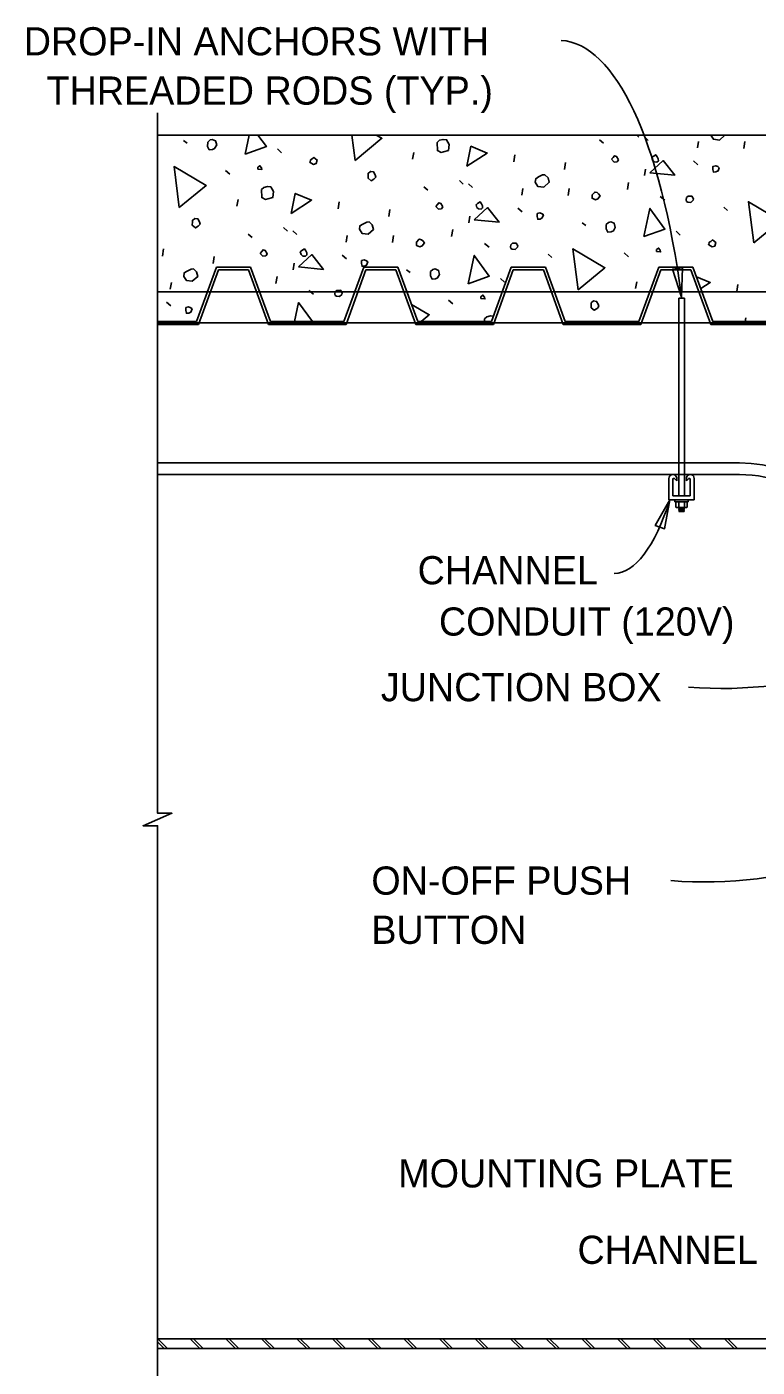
# Model space of a CAD drawing. Extents: x 927736.2 to 927809.6, y 636703.6 to 636757.7.
# Drawn here: x 927784.6 to 927794.26, y 636715.22 to 636732.95 of the extents above; entities that cross this region are included whole.
import ezdxf

# ---------------------------------------------------------------- set-up
doc = ezdxf.new("R2010")
doc.units = 0
for name, color, linetype in [('DimLines_dp', 7, 'Continuous'), ('Miscellaneous1', 7, 'Continuous'), ('Miscellaneous2', 7, 'Continuous'), ('Miscellaneous3', 7, 'Continuous')]:
    doc.layers.add(name, color=color, linetype=linetype)

msp = doc.modelspace()

# ---------------------------------------------------------------- linework, layer by layer
at = {"layer": 'DimLines_dp'}
msp.add_lwpolyline([(927786.333, 636713.104), (927786.333, 636722.378), (927786.142, 636722.378), (927786.333, 636722.461), (927786.524, 636722.544), (927786.333, 636722.544), (927786.333, 636731.807)], dxfattribs=at)
for points in [[(927793.262, 636729.37), (927793.144, 636729.742), (927793.273, 636729.76)], [(927793.108, 636726.69), (927792.915, 636726.351), (927793.038, 636726.306)]]:
    msp.add_lwpolyline(points, close=True, dxfattribs=at)
for centre in [(927793.802, 636729.733), (927793.57, 636727.173)]:
    msp.add_arc(centre, 5.539, 265.3641, 288.9731, dxfattribs=at)
for centre, major_axis, ratio, start_param, end_param in [((927791.283, 636725.568), (-0.388, -7.199), 0.2923, 2.142822, 3.141563), ((927792.341, 636729.829), (-0.032, 4.113), 0.280094, 3.141615, 3.84244)]:
    msp.add_ellipse(centre, major_axis=major_axis, ratio=ratio, start_param=start_param, end_param=end_param, dxfattribs=at)
at = {"layer": 'Miscellaneous1'}
for p, q in [((927794.029, 636727.179), (927786.333, 636727.179)), ((927794.029, 636727.024), (927786.333, 636727.024)), ((927793.095, 636726.973), (927793.095, 636726.69)), ((927793.146, 636726.742), (927793.146, 636726.961)), ((927793.168, 636726.97), (927793.198, 636726.941)), ((927793.198, 636726.985), (927793.192, 636726.996)), ((927793.198, 636726.941), (927793.198, 636726.985)), ((927793.332, 636726.996), (927793.326, 636726.985)), ((927793.326, 636726.985), (927793.326, 636726.941)), ((927793.326, 636726.941), (927793.356, 636726.97)), ((927793.378, 636726.961), (927793.378, 636726.742)), ((927793.429, 636726.69), (927793.429, 636726.973)), ((927793.095, 636726.69), (927793.429, 636726.69)), ((927793.378, 636726.742), (927793.146, 636726.742))]:
    msp.add_line(p, q, dxfattribs=at)
for centre, radius, start, end in [((927794.029, 636725.374), 1.804, 14.3572, 89.9857), ((927793.146, 636726.973), 0.0513, 26.1794, 179.9999), ((927793.159, 636726.961), 0.0128, 45, 180), ((927793.378, 636726.973), 0.0513, 0.0001, 153.8206), ((927793.365, 636726.961), 0.0128, 360, 135), ((927794.029, 636725.374), 1.65, 0, 90)]:
    msp.add_arc(centre, radius, start, end, dxfattribs=at)
at = {"layer": 'Miscellaneous2'}
for p, q in [((927786.333, 636731.515), (927803.622, 636731.515)), ((927786.677, 636731.445), (927786.725, 636731.407)), ((927792.178, 636731.451), (927792.228, 636731.407)), ((927792.67, 636731.515), (927792.698, 636731.488)), ((927792.767, 636731.494), (927792.819, 636731.444)), ((927793.471, 636731.344), (927793.486, 636731.431)), ((927794.086, 636731.337), (927794.099, 636731.43)), ((927787.92, 636731.332), (927787.972, 636731.282)), ((927789.705, 636731.197), (927789.72, 636731.284)), ((927791.043, 636731.16), (927791.057, 636731.253)), ((927787.231, 636731.045), (927787.289, 636730.997)), ((927791.715, 636731.059), (927791.729, 636731.152)), ((927792.771, 636730.978), (927792.786, 636731.065)), ((927793.422, 636731.172), (927793.479, 636731.123)), ((927790.324, 636730.916), (927790.375, 636730.866)), ((927790.444, 636730.872), (927790.496, 636730.822)), ((927792.545, 636730.796), (927792.559, 636730.889)), ((927789.855, 636730.829), (927789.905, 636730.785)), ((927791.148, 636730.722), (927791.163, 636730.809)), ((927791.763, 636730.714), (927791.776, 636730.807)), ((927792.979, 636730.702), (927793.043, 636730.655)), ((927787.382, 636730.575), (927787.397, 636730.662)), ((927788.72, 636730.537), (927788.734, 636730.63)), ((927789.392, 636730.437), (927789.406, 636730.53)), ((927791.099, 636730.549), (927791.156, 636730.501)), ((927793.821, 636730.563), (927793.871, 636730.519)), ((927790.448, 636730.356), (927790.463, 636730.443)), ((927791.948, 636730.355), (927791.997, 636730.317)), ((927787.532, 636730.206), (927787.582, 636730.162)), ((927788, 636730.293), (927788.052, 636730.244)), ((927788.121, 636730.249), (927788.173, 636730.199)), ((927788.825, 636730.099), (927788.84, 636730.186)), ((927789.44, 636730.092), (927789.453, 636730.185)), ((927790.222, 636730.174), (927790.236, 636730.267)), ((927793.192, 636730.242), (927793.244, 636730.192)), ((927786.397, 636729.915), (927786.411, 636730.008)), ((927790.656, 636730.079), (927790.72, 636730.033)), ((927787.069, 636729.814), (927787.083, 636729.907)), ((927788.125, 636729.733), (927788.14, 636729.82)), ((927788.775, 636729.927), (927788.833, 636729.878)), ((927791.498, 636729.941), (927791.548, 636729.897)), ((927792.503, 636729.955), (927792.56, 636729.906)), ((927786.849, 636729.048), (927787.111, 636729.768)), ((927786.876, 636729.01), (927787.137, 636729.73)), ((927787.563, 636729.768), (927787.111, 636729.768)), ((927787.536, 636729.73), (927787.137, 636729.73)), ((927787.798, 636729.01), (927787.536, 636729.73)), ((927787.825, 636729.048), (927787.563, 636729.768)), ((927787.899, 636729.551), (927787.913, 636729.644)), ((927788.798, 636729.048), (927789.06, 636729.768)), ((927788.825, 636729.01), (927789.087, 636729.73)), ((927789.512, 636729.768), (927789.06, 636729.768)), ((927789.485, 636729.73), (927789.087, 636729.73)), ((927789.747, 636729.01), (927789.485, 636729.73)), ((927789.774, 636729.048), (927789.512, 636729.768)), ((927789.625, 636729.733), (927789.674, 636729.695)), ((927790.748, 636729.048), (927791.01, 636729.768)), ((927790.775, 636729.01), (927791.037, 636729.73)), ((927790.869, 636729.619), (927790.921, 636729.569)), ((927791.462, 636729.768), (927791.01, 636729.768)), ((927791.435, 636729.73), (927791.037, 636729.73)), ((927791.697, 636729.01), (927791.435, 636729.73)), ((927791.724, 636729.048), (927791.462, 636729.768)), ((927792.698, 636729.048), (927792.96, 636729.768)), ((927792.725, 636729.01), (927792.987, 636729.73)), ((927793.412, 636729.768), (927792.96, 636729.768)), ((927793.385, 636729.73), (927792.987, 636729.73)), ((927793.647, 636729.01), (927793.385, 636729.73)), ((927793.674, 636729.048), (927793.412, 636729.768)), ((927786.502, 636729.477), (927786.517, 636729.564)), ((927788.333, 636729.457), (927788.397, 636729.41)), ((927792.654, 636729.485), (927792.669, 636729.572)), ((927793.992, 636729.447), (927794.005, 636729.54)), ((927786.452, 636729.304), (927786.51, 636729.256)), ((927790.18, 636729.332), (927790.237, 636729.284)), ((927794.103, 636729.048), (927794.112, 636729.096)), ((927786.849, 636729.048), (927786.333, 636729.048)), ((927786.876, 636729.01), (927786.333, 636729.01)), ((927788.825, 636729.01), (927787.798, 636729.01)), ((927788.798, 636729.048), (927787.825, 636729.048)), ((927790.775, 636729.01), (927789.747, 636729.01)), ((927790.748, 636729.048), (927789.774, 636729.048)), ((927789.863, 636729.01), (927790.659, 636729.01)), ((927792.725, 636729.01), (927791.697, 636729.01)), ((927792.698, 636729.048), (927791.724, 636729.048)), ((927792.622, 636729.01), (927791.8, 636729.01)), ((927794.675, 636729.01), (927793.647, 636729.01)), ((927794.648, 636729.048), (927793.674, 636729.048))]:
    msp.add_line(p, q, dxfattribs=at)
for points in [[(927786.996, 636731.422), (927786.992, 636731.364), (927787.017, 636731.32), (927787.06, 636731.325), (927787.088, 636731.339), (927787.115, 636731.384), (927787.1, 636731.438), (927787.056, 636731.458), (927787.027, 636731.45), (927786.996, 636731.422)], [(927787.492, 636731.262), (927787.546, 636731.515)], [(927787.659, 636731.515), (927787.772, 636731.362), (927787.492, 636731.262)], [(927788.944, 636731.178), (927788.902, 636731.515)], [(927789.226, 636731.515), (927789.3, 636731.472), (927788.944, 636731.178)], [(927790.029, 636731.418), (927790.033, 636731.31), (927790.084, 636731.286), (927790.114, 636731.294), (927790.179, 636731.311), (927790.19, 636731.391), (927790.154, 636731.452), (927790.108, 636731.458), (927790.06, 636731.446), (927790.029, 636731.418)], [(927793.649, 636731.513), (927793.683, 636731.459), (927793.762, 636731.448), (927793.835, 636731.512), (927793.834, 636731.515)], [(927793.649, 636731.515), (927793.649, 636731.513)], [(927788.351, 636731.154), (927788.396, 636731.127), (927788.432, 636731.137), (927788.445, 636731.185), (927788.398, 636731.217), (927788.377, 636731.199), (927788.355, 636731.186), (927788.351, 636731.154), (927788.348, 636731.165)], [(927790.421, 636731.102), (927790.477, 636731.366), (927790.693, 636731.277), (927790.421, 636731.102)], [(927792.337, 636731.194), (927792.372, 636731.158), (927792.409, 636731.162), (927792.428, 636731.186), (927792.425, 636731.198), (927792.403, 636731.231), (927792.375, 636731.242), (927792.356, 636731.218), (927792.337, 636731.194)], [(927792.877, 636731.179), (927792.901, 636731.16), (927792.934, 636731.156), (927792.955, 636731.174), (927792.954, 636731.2), (927792.94, 636731.228), (927792.921, 636731.254), (927792.888, 636731.233), (927792.867, 636731.215), (927792.877, 636731.179)], [(927786.621, 636730.556), (927786.552, 636731.099), (927786.977, 636730.849), (927786.621, 636730.556)], [(927787.66, 636731.064), (927787.712, 636731.059), (927787.706, 636731.083), (927787.686, 636731.109), (927787.659, 636731.09), (927787.66, 636731.064)], [(927792.844, 636731.017), (927793.018, 636731.178), (927793.172, 636730.983), (927792.844, 636731.017)], [(927793.675, 636731.061), (927793.684, 636731.025), (927793.716, 636731.027), (927793.744, 636731.041), (927793.758, 636731.083), (927793.741, 636731.098), (927793.713, 636731.109), (927793.677, 636731.1), (927793.675, 636731.061)], [(927789.117, 636730.988), (927789.116, 636730.944), (927789.157, 636730.91), (927789.195, 636730.933), (927789.22, 636730.959), (927789.212, 636730.989), (927789.189, 636731.027), (927789.149, 636731.035), (927789.118, 636731.008), (927789.117, 636730.988)], [(927791.326, 636730.891), (927791.36, 636730.836), (927791.439, 636730.826), (927791.512, 636730.89), (927791.496, 636730.949), (927791.453, 636730.989), (927791.422, 636730.987), (927791.371, 636730.961), (927791.333, 636730.937), (927791.326, 636730.891)], [(927787.706, 636730.796), (927787.71, 636730.688), (927787.761, 636730.663), (927787.791, 636730.671), (927787.856, 636730.689), (927787.867, 636730.768), (927787.831, 636730.829), (927787.785, 636730.836), (927787.737, 636730.823), (927787.706, 636730.796)], [(927788.098, 636730.479), (927788.154, 636730.743), (927788.37, 636730.654), (927788.098, 636730.479)], [(927792.08, 636730.723), (927792.079, 636730.678), (927792.123, 636730.658), (927792.157, 636730.673), (927792.185, 636730.712), (927792.165, 636730.739), (927792.148, 636730.754), (927792.121, 636730.759), (927792.109, 636730.756), (927792.08, 636730.723)], [(927793.329, 636730.636), (927793.344, 636730.627), (927793.383, 636730.625), (927793.414, 636730.652), (927793.421, 636730.673), (927793.4, 636730.706), (927793.349, 636730.705), (927793.328, 636730.687), (927793.323, 636730.66), (927793.329, 636730.636)], [(927790.014, 636730.571), (927790.049, 636730.536), (927790.086, 636730.539), (927790.105, 636730.564), (927790.102, 636730.576), (927790.08, 636730.608), (927790.052, 636730.62), (927790.033, 636730.595), (927790.014, 636730.571)], [(927790.521, 636730.394), (927790.695, 636730.556), (927790.849, 636730.361), (927790.521, 636730.394)], [(927790.554, 636730.556), (927790.578, 636730.537), (927790.611, 636730.533), (927790.632, 636730.552), (927790.631, 636730.577), (927790.617, 636730.605), (927790.598, 636730.632), (927790.565, 636730.61), (927790.544, 636730.592), (927790.554, 636730.556)], [(927792.764, 636730.172), (927792.843, 636730.544), (927793.043, 636730.272), (927792.764, 636730.172)], [(927794.216, 636730.088), (927794.147, 636730.632), (927794.572, 636730.382), (927794.216, 636730.088)], [(927786.794, 636730.366), (927786.793, 636730.321), (927786.834, 636730.287), (927786.872, 636730.31), (927786.897, 636730.336), (927786.889, 636730.366), (927786.866, 636730.405), (927786.826, 636730.413), (927786.795, 636730.385), (927786.794, 636730.366)], [(927789.003, 636730.268), (927789.037, 636730.214), (927789.116, 636730.203), (927789.189, 636730.267), (927789.173, 636730.327), (927789.13, 636730.366), (927789.099, 636730.364), (927789.048, 636730.338), (927789.01, 636730.315), (927789.003, 636730.268)], [(927791.352, 636730.438), (927791.361, 636730.402), (927791.393, 636730.404), (927791.421, 636730.418), (927791.435, 636730.46), (927791.418, 636730.475), (927791.39, 636730.487), (927791.354, 636730.477), (927791.352, 636730.438)], [(927792.267, 636730.332), (927792.264, 636730.274), (927792.289, 636730.23), (927792.332, 636730.235), (927792.36, 636730.249), (927792.386, 636730.294), (927792.372, 636730.348), (927792.328, 636730.368), (927792.298, 636730.36), (927792.267, 636730.332)], [(927787.691, 636729.949), (927787.726, 636729.913), (927787.763, 636729.917), (927787.782, 636729.941), (927787.779, 636729.953), (927787.757, 636729.986), (927787.729, 636729.997), (927787.71, 636729.973), (927787.691, 636729.949)], [(927788.231, 636729.934), (927788.255, 636729.915), (927788.288, 636729.911), (927788.309, 636729.929), (927788.308, 636729.955), (927788.294, 636729.983), (927788.274, 636730.009), (927788.242, 636729.988), (927788.221, 636729.97), (927788.231, 636729.934)], [(927789.757, 636730.1), (927789.756, 636730.055), (927789.8, 636730.035), (927789.834, 636730.051), (927789.862, 636730.09), (927789.842, 636730.117), (927789.825, 636730.131), (927789.798, 636730.137), (927789.786, 636730.134), (927789.757, 636730.1)], [(927791.006, 636730.013), (927791.021, 636730.005), (927791.06, 636730.002), (927791.091, 636730.03), (927791.098, 636730.051), (927791.076, 636730.083), (927791.026, 636730.083), (927791.005, 636730.064), (927790.999, 636730.037), (927791.006, 636730.013)], [(927791.893, 636729.466), (927791.824, 636730.009), (927792.249, 636729.759), (927791.893, 636729.466)], [(927792.932, 636729.974), (927792.984, 636729.969), (927792.978, 636729.993), (927792.958, 636730.019), (927792.931, 636729.999), (927792.932, 636729.974)], [(927793.623, 636730.063), (927793.668, 636730.037), (927793.704, 636730.047), (927793.716, 636730.095), (927793.67, 636730.127), (927793.649, 636730.109), (927793.627, 636730.096), (927793.623, 636730.063), (927793.62, 636730.075)], [(927788.198, 636729.772), (927788.372, 636729.933), (927788.526, 636729.738), (927788.198, 636729.772)], [(927789.029, 636729.816), (927789.038, 636729.78), (927789.07, 636729.782), (927789.098, 636729.796), (927789.112, 636729.838), (927789.095, 636729.853), (927789.067, 636729.864), (927789.031, 636729.855), (927789.029, 636729.816)], [(927790.441, 636729.549), (927790.52, 636729.922), (927790.72, 636729.65), (927790.441, 636729.549)], [(927786.68, 636729.646), (927786.714, 636729.591), (927786.793, 636729.581), (927786.866, 636729.645), (927786.85, 636729.704), (927786.807, 636729.744), (927786.776, 636729.742), (927786.725, 636729.716), (927786.687, 636729.693), (927786.68, 636729.646)], [(927789.944, 636729.71), (927789.941, 636729.652), (927789.966, 636729.607), (927790.009, 636729.612), (927790.037, 636729.626), (927790.063, 636729.672), (927790.049, 636729.725), (927790.005, 636729.745), (927789.975, 636729.737), (927789.944, 636729.71)], [(927793.459, 636729.64), (927793.642, 636729.564), (927793.516, 636729.483)], [(927788.683, 636729.391), (927788.698, 636729.382), (927788.737, 636729.38), (927788.768, 636729.407), (927788.775, 636729.428), (927788.753, 636729.461), (927788.703, 636729.46), (927788.682, 636729.442), (927788.676, 636729.415), (927788.683, 636729.391)], [(927788.144, 636729.048), (927788.197, 636729.299), (927788.382, 636729.048)], [(927789.692, 636729.274), (927789.926, 636729.137), (927789.819, 636729.048)], [(927790.609, 636729.352), (927790.661, 636729.347), (927790.655, 636729.37), (927790.635, 636729.397), (927790.608, 636729.377), (927790.609, 636729.352)], [(927792.065, 636729.276), (927792.065, 636729.231), (927792.106, 636729.197), (927792.144, 636729.22), (927792.169, 636729.246), (927792.161, 636729.276), (927792.138, 636729.315), (927792.097, 636729.323), (927792.067, 636729.295), (927792.065, 636729.276)], [(927786.706, 636729.193), (927786.715, 636729.157), (927786.747, 636729.159), (927786.775, 636729.173), (927786.789, 636729.216), (927786.772, 636729.23), (927786.744, 636729.242), (927786.708, 636729.232), (927786.706, 636729.193)], [(927790.773, 636729.118), (927790.734, 636729.123), (927790.686, 636729.111), (927790.655, 636729.083)], [(927790.655, 636729.083), (927790.656, 636729.048)]]:
    msp.add_lwpolyline(points, dxfattribs=at)
at = {"layer": 'Miscellaneous3'}
for p, q in [((927786.333, 636729.44), (927787.032, 636729.44)), ((927787.641, 636729.44), (927787.032, 636729.44)), ((927787.641, 636729.44), (927788.982, 636729.44)), ((927789.591, 636729.44), (927788.982, 636729.44)), ((927789.591, 636729.44), (927790.932, 636729.44)), ((927791.541, 636729.44), (927790.932, 636729.44)), ((927791.541, 636729.44), (927792.881, 636729.44)), ((927793.49, 636729.44), (927792.881, 636729.44)), ((927793.224, 636726.742), (927793.224, 636729.357)), ((927793.224, 636729.357), (927793.301, 636729.357)), ((927793.301, 636726.742), (927793.301, 636729.357)), ((927793.49, 636729.44), (927794.831, 636729.44)), ((927786.333, 636729.029), (927786.882, 636729.029)), ((927787.791, 636729.029), (927786.882, 636729.029)), ((927787.791, 636729.029), (927788.832, 636729.029)), ((927789.741, 636729.029), (927788.832, 636729.029)), ((927789.741, 636729.029), (927790.782, 636729.029)), ((927791.69, 636729.029), (927790.782, 636729.029)), ((927791.69, 636729.029), (927792.732, 636729.029)), ((927793.64, 636729.029), (927792.732, 636729.029)), ((927793.64, 636729.029), (927794.681, 636729.029)), ((927793.188, 636726.593), (927793.188, 636726.663)), ((927793.188, 636726.663), (927793.336, 636726.663)), ((927793.225, 636726.593), (927793.225, 636726.663)), ((927793.299, 636726.593), (927793.299, 636726.663)), ((927793.336, 636726.593), (927793.336, 636726.663)), ((927793.206, 636726.587), (927793.318, 636726.587)), ((927793.223, 636726.586), (927793.24, 636726.587)), ((927793.223, 636726.586), (927793.226, 636726.587)), ((927793.236, 636726.581), (927793.223, 636726.586)), ((927793.223, 636726.573), (927793.236, 636726.581)), ((927793.223, 636726.573), (927793.3, 636726.58)), ((927793.236, 636726.568), (927793.223, 636726.573)), ((927793.223, 636726.56), (927793.236, 636726.568)), ((927793.223, 636726.56), (927793.3, 636726.567)), ((927793.236, 636726.555), (927793.223, 636726.56)), ((927793.223, 636726.548), (927793.236, 636726.555)), ((927793.223, 636726.548), (927793.3, 636726.554)), ((927793.236, 636726.542), (927793.223, 636726.548)), ((927793.228, 636726.537), (927793.236, 636726.542)), ((927793.228, 636726.537), (927793.293, 636726.537)), ((927793.253, 636726.537), (927793.3, 636726.541)), ((927793.287, 636726.585), (927793.291, 636726.587)), ((927793.3, 636726.58), (927793.287, 636726.585)), ((927793.287, 636726.572), (927793.3, 636726.58)), ((927793.3, 636726.567), (927793.287, 636726.572)), ((927793.287, 636726.56), (927793.3, 636726.567)), ((927793.3, 636726.554), (927793.287, 636726.56)), ((927793.287, 636726.547), (927793.3, 636726.554)), ((927793.3, 636726.541), (927793.287, 636726.547)), ((927793.293, 636726.537), (927793.3, 636726.541)), ((927786.333, 636715.591), (927803.622, 636715.591)), ((927786.422, 636715.462), (927786.333, 636715.551)), ((927786.333, 636715.462), (927803.622, 636715.462)), ((927786.465, 636715.462), (927786.337, 636715.591)), ((927786.893, 636715.462), (927786.764, 636715.591)), ((927786.936, 636715.462), (927786.808, 636715.591)), ((927787.364, 636715.462), (927787.235, 636715.591)), ((927787.407, 636715.462), (927787.279, 636715.591)), ((927787.834, 636715.462), (927787.706, 636715.591)), ((927787.878, 636715.462), (927787.749, 636715.591)), ((927788.305, 636715.462), (927788.177, 636715.591)), ((927788.349, 636715.462), (927788.22, 636715.591)), ((927788.776, 636715.462), (927788.648, 636715.591)), ((927788.82, 636715.462), (927788.691, 636715.591)), ((927789.247, 636715.462), (927789.119, 636715.591)), ((927789.291, 636715.462), (927789.162, 636715.591)), ((927789.718, 636715.462), (927789.59, 636715.591)), ((927789.762, 636715.462), (927789.633, 636715.591)), ((927790.189, 636715.462), (927790.061, 636715.591)), ((927790.233, 636715.462), (927790.104, 636715.591)), ((927790.66, 636715.462), (927790.531, 636715.591)), ((927790.704, 636715.462), (927790.575, 636715.591)), ((927791.131, 636715.462), (927791.002, 636715.591)), ((927791.175, 636715.462), (927791.046, 636715.591)), ((927791.602, 636715.462), (927791.473, 636715.591)), ((927791.646, 636715.462), (927791.517, 636715.591)), ((927792.073, 636715.462), (927791.944, 636715.591)), ((927792.116, 636715.462), (927791.988, 636715.591)), ((927792.544, 636715.462), (927792.415, 636715.591)), ((927792.587, 636715.462), (927792.459, 636715.591)), ((927793.015, 636715.462), (927792.886, 636715.591)), ((927793.058, 636715.462), (927792.93, 636715.591)), ((927793.486, 636715.462), (927793.357, 636715.591)), ((927793.529, 636715.462), (927793.401, 636715.591)), ((927793.957, 636715.462), (927793.828, 636715.591)), ((927794, 636715.462), (927793.872, 636715.591))]:
    msp.add_line(p, q, dxfattribs=at)
msp.add_lwpolyline([(927793.349, 636726.69), (927793.349, 636726.663), (927793.175, 636726.663), (927793.175, 636726.69)], close=True, dxfattribs=at)
for centre, radius, start, end in [((927793.206, 636726.621), 0.034, 236.9791, 303.0209), ((927793.262, 636726.715), 0.128, 253.1396, 286.8604), ((927793.318, 636726.621), 0.034, 236.9791, 303.0209)]:
    msp.add_arc(centre, radius, start, end, dxfattribs=at)

# ---------------------------------------------------------------- texts
at = {"layer": 'DimLines_dp'}
for s, height, p in [('DROP-IN ANCHORS WITH', 0.37296, (927784.564, 636732.569)), ('THREADED RODS (TYP.)', 0.37296, (927784.865, 636731.917)), ('CHANNEL', 0.373, (927789.772, 636725.572)), ('CONDUIT (120V)', 0.37296, (927790.054, 636724.893)), ('JUNCTION BOX', 0.37296, (927789.286, 636724.025)), ('ON-OFF PUSH ', 0.37296, (927789.16, 636721.466)), ('BUTTON', 0.373, (927789.16, 636720.815)), ('MOUNTING PLATE', 0.37296, (927789.516, 636717.593)), ('CHANNEL', 0.373, (927791.886, 636716.582))]:
    msp.add_text(s, height=height, dxfattribs=at).set_placement(p)

doc.saveas('drawing.dxf')
